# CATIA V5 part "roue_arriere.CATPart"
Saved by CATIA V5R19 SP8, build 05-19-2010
Part number: roue_arrière
Bounding box of the stored display mesh (mm): x -149.855 to 149.855, y -149.997 to 149.997, z -25 to 25
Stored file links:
  U:\Thinkmotion\Assemblage final\roue_arriere.CATPart
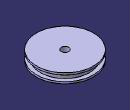
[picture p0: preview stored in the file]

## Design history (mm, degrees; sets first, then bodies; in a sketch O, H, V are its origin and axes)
Body1 (main body)
  Sketch1 on yz-plane, origin (0, 0, 0), H (0, 1, 0), V (0, 0, 1)
    point P1 (0, 25)
    line L1 (0, 25) -> (-150, 25)
    point P2 (-150, 25)
    line L2 (-150, 25) -> (-150, 15)
    point P3 (-150, 15)
    line L3 (-150, 15) -> (-130, 15)
    point P4 (-130, 15)
    line L4 (-130, 15) -> (-130, 0)
    point P5 (-130, 0)
    line L5 (0, 0) -> (0, 25)
    point P6 (0, -25)
    point P7 (-150, -25)
    point P8 (-150, -15)
    point P9 (-130, -15)
    point P10 (-130, 0)
    line L6 (0, -25) -> (-150, -25)
    line L7 (-150, -25) -> (-150, -15)
    line L8 (-150, -15) -> (-130, -15)
    line L9 (-130, -15) -> (-130, 0)
    point P11 (0, 0)
    line L10 (0, 0) -> (0, -25)
    length L1 = 150
    length L3 = 20
    length L2 = 10
    coincidence: P1 V, O P11, P5 P10
    horizontal: L1 H, L3 H
    vertical: L2 V, L4 V, L5 V
    symmetry: P1 P6 H, P2 P7 H, P3 P8 H, P4 P9 H, P5 P10 H, L1 L6 H, L2 L7 H, L3 L8 H, L4 L9 H, O P11 H, L5 L10 H
  Shaft1: profile Sketch1, axis Sketch1.L5, angle 360
  Sketch2 on face of Shaft1 from Sketch1.L1, origin (0, 0, 25), H (1, 0, 0), V (0, 1, 0)
    point P1 (0, 0)
    coincidence: P1 O
  Hole1: placed by Sketch2, at (0, 0, 25) direction (0, 0, -1), diameter 40, through (limit type 3)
